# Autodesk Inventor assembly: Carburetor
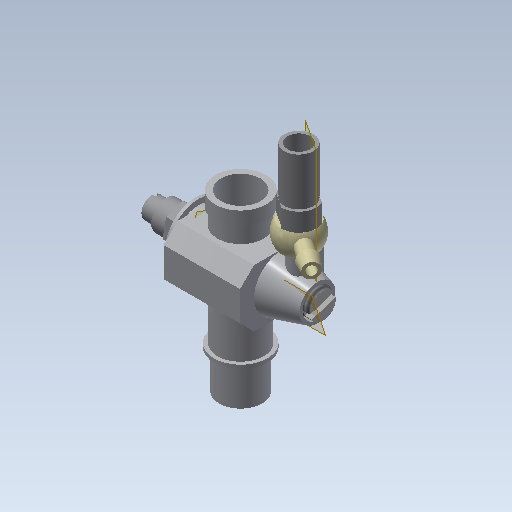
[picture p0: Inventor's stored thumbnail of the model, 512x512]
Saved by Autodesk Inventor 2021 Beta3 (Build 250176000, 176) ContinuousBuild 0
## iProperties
Created: 2012-08
Part Number: Carburetor
Document SubType Name: Assembly
Designer: John
Author: John
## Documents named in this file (8)
- C:\Users\John Helfen\Desktop\Ex_Files_Autodesk_Inventor_2020_EssT\Ex_Files_Autodesk_Inventor_2021_EssT\Exercise Files\03_Navigating the interface\03_03\Carburetor.iam
- C:\Users\John Helfen\Desktop\Ex_Files_Autodesk_Inventor_2020_EssT\Ex_Files_Autodesk_Inventor_2021_EssT\Exercise Files\03_Navigating the interface\03_03\Gas Regulator.ipt
- C:\Users\John Helfen\Desktop\Ex_Files_Autodesk_Inventor_2020_EssT\Ex_Files_Autodesk_Inventor_2021_EssT\Exercise Files\03_Navigating the interface\03_03\Mixture Control.ipt
- C:\Users\John Helfen\Desktop\Ex_Files_Autodesk_Inventor_2020_EssT\Ex_Files_Autodesk_Inventor_2021_EssT\Exercise Files\03_Navigating the interface\03_03\Air Adjuster.ipt
- C:\Users\John Helfen\Desktop\Ex_Files_Autodesk_Inventor_2020_EssT\Ex_Files_Autodesk_Inventor_2021_EssT\Exercise Files\03_Navigating the interface\03_03\Hex Cap.ipt
- C:\Users\John Helfen\Desktop\Ex_Files_Autodesk_Inventor_2020_EssT\Ex_Files_Autodesk_Inventor_2021_EssT\Exercise Files\03_Navigating the interface\03_03\Fuel Intake.ipt
- C:\Users\John Helfen\Desktop\Ex_Files_Autodesk_Inventor_2020_EssT\Ex_Files_Autodesk_Inventor_2021_EssT\Exercise Files\03_Navigating the interface\03_03\Fuel Adjuster.ipt
- C:\Users\John Helfen\Desktop\Ex_Files_Autodesk_Inventor_2020_EssT\Ex_Files_Autodesk_Inventor_2021_EssT\Exercise Files\03_Navigating the interface\03_03\Carburetor Housing_v3.ipt
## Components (7 placed, 7 different names)
1. Carburetor Housing_v3:2 — Mate:6, Mate:7, Mate:10, Flush:1, Flush:2
2. Gas Regulator:1 — Mate:6, Flush:1
3. Mixture Control:1 — Flush:2
4. Air Adjuster:1
5. Hex Cap:1
6. Fuel Intake:1 — Mate:8, Mate:9, Mate:10
7. Fuel Adjuster:1 — Mate:7, Mate:8, Mate:9
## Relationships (7: Mate 5, Flush 2)
- Mate:6: Carburetor Housing_v3:2 ↔ Gas Regulator:1
- Mate:7: Carburetor Housing_v3:2 ↔ Fuel Adjuster:1
- Mate:8: Fuel Intake:1 ↔ Fuel Adjuster:1
- Mate:9: Fuel Intake:1 ↔ Fuel Adjuster:1
- Mate:10: Carburetor Housing_v3:2 ↔ Fuel Intake:1
- Flush:1: Carburetor Housing_v3:2 ↔ Gas Regulator:1
- Flush:2: Carburetor Housing_v3:2 ↔ Mixture Control:1
